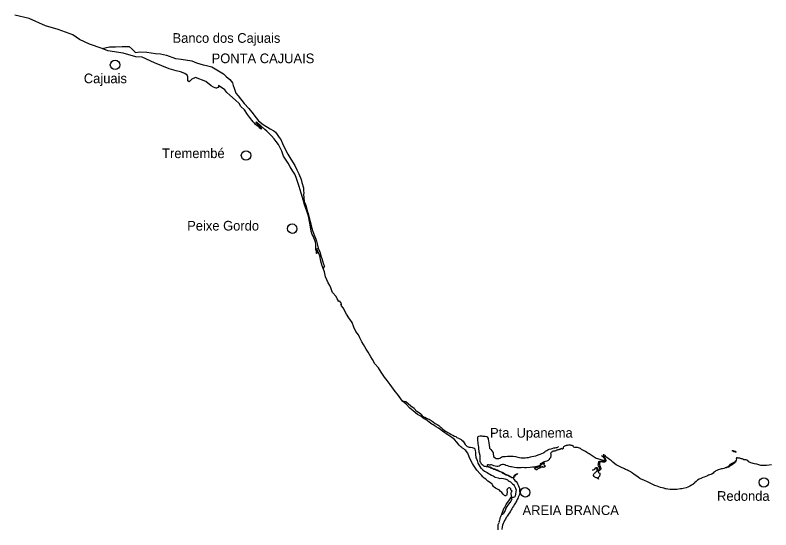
# Model space of a CAD drawing. Extents: x 662444 to 1640468, y 7452018 to 9606170.
# Drawn here: x 1338677 to 1392360, y 9444693 to 9481286 of the extents above; entities that cross this region are included whole.
import ezdxf

# ---------------------------------------------------------------- set-up
doc = ezdxf.new("R2010")
doc.units = 0
for name, color, linetype in [('Level 1', 7, 'Continuous'), ('Level 2', 7, 'Continuous'), ('Level 3', 7, 'Continuous')]:
    doc.layers.add(name, color=color, linetype=linetype)

msp = doc.modelspace()

# ---------------------------------------------------------------- linework, layer by layer
at = {"layer": 'Level 1'}
for points in [[(1343968, 9479211), (1343241, 9479552), (1342767, 9479891), (1341741, 9480268), (1340827, 9480522), (1339680, 9481054), (1338660, 9481286)], [(1352611, 9476253), (1352225, 9476558), (1351497, 9476851), (1351236, 9476724), (1351040, 9476548), (1350934, 9476622), (1350938, 9476906), (1350907, 9477028), (1350731, 9477144), (1350431, 9477244), (1350124, 9477321), (1349614, 9477465), (1348571, 9477892), (1347708, 9478299), (1347253, 9478321), (1346355, 9478583), (1345253, 9478742), (1344858, 9478909), (1343968, 9479211)], [(1344858, 9478909), (1345388, 9479041), (1345817, 9479027), (1346273, 9479062), (1346491, 9479060), (1346784, 9479064), (1347001, 9478865), (1347226, 9478636)], [(1347226, 9478636), (1347534, 9478676), (1348038, 9478644), (1348649, 9478563), (1349003, 9478532), (1349430, 9478431), (1350066, 9478211), (1350472, 9478156), (1351235, 9478026), (1351561, 9477900), (1352041, 9477758), (1352262, 9477695), (1352639, 9477607), (1353478, 9477121), (1353677, 9476922), (1353939, 9476701), (1354129, 9476469), (1354158, 9476279), (1354232, 9476086), (1354360, 9475729), (1354514, 9475552), (1354945, 9475012), (1355286, 9474637), (1355581, 9474263), (1355627, 9474189), (1355971, 9473777), (1356300, 9473517), (1356798, 9473190), (1357063, 9473051), (1357163, 9472966), (1357281, 9472791), (1357434, 9472595), (1357555, 9472448), (1357665, 9472148), (1357866, 9471762), (1358055, 9471397), (1358256, 9471035), (1358538, 9470606), (1358688, 9470297), (1358828, 9470009), (1358989, 9469602), (1359047, 9469392), (1359152, 9469017), (1359169, 9468847), (1359190, 9468596), (1359162, 9468567), (1359185, 9468300), (1359217, 9468047), (1359278, 9467886), (1359351, 9467686), (1359397, 9467466), (1359451, 9467299), (1359493, 9467178), (1359615, 9466674), (1359659, 9466543), (1359706, 9466316), (1359745, 9466150), (1359805, 9465967), (1359948, 9465597), (1360024, 9465420), (1360096, 9465212), (1360158, 9464923), (1360210, 9464711), (1360298, 9464516), (1360355, 9464389), (1360397, 9464171), (1360469, 9463981), (1360514, 9463808), (1360577, 9463586), (1360664, 9463436), (1360564, 9463269)], [(1361860, 9460803), (1361803, 9460824), (1361821, 9460847), (1361760, 9460886), (1361775, 9460917), (1361719, 9460925), (1361719, 9460945), (1361688, 9460976), (1361667, 9460925), (1361631, 9460958), (1361616, 9461012), (1361547, 9461108), (1361478, 9461287), (1361225, 9461562), (1361169, 9461689), (1361108, 9461889), (1361024, 9462077), (1360909, 9462249), (1360822, 9462463), (1360723, 9462686), (1360647, 9463030), (1360564, 9463269), (1360464, 9463539), (1360385, 9463806), (1360315, 9464163), (1360160, 9464544), (1360134, 9464647), (1360103, 9464699), (1360109, 9464601), (1360119, 9464488), (1360118, 9464338), (1360092, 9464344), (1360093, 9464457), (1360074, 9464524), (1360047, 9464572), (1360032, 9464724), (1360033, 9464888), (1360027, 9465012), (1360003, 9465153), (1359949, 9465335), (1359850, 9465580), (1359783, 9465698), (1359698, 9465937), (1359647, 9466235), (1359610, 9466489), (1359516, 9467002), (1359407, 9467357), (1359295, 9467614), (1359240, 9467794), (1359155, 9468072), (1358996, 9468617), (1358856, 9469111), (1358737, 9469457), (1358640, 9469740), (1358553, 9469976), (1358408, 9470204), (1358204, 9470511), (1358081, 9470760), (1357751, 9471267), (1357632, 9471619), (1357390, 9472092), (1357217, 9472298), (1357087, 9472490), (1356881, 9472712), (1356555, 9473031), (1356414, 9473147), (1355850, 9473664), (1355786, 9473654), (1355776, 9473636), (1355822, 9473598), (1355860, 9473552), (1355942, 9473481), (1356042, 9473389), (1356153, 9473274), (1356173, 9473209), (1356155, 9473189), (1356132, 9473199), (1356067, 9473258), (1356019, 9473310), (1355872, 9473425), (1355750, 9473513), (1355673, 9473595), (1355576, 9473706), (1355317, 9474035), (1355174, 9474225), (1354965, 9474558), (1354716, 9474789), (1354596, 9475010), (1354327, 9475236), (1353930, 9475589), (1353715, 9475789), (1353574, 9475981), (1353133, 9476271), (1353112, 9476253), (1353120, 9476149), (1353079, 9476140), (1352989, 9476104), (1352951, 9476089), (1352884, 9476108), (1352770, 9476172), (1352611, 9476253)], [(1367500, 9452769), (1367270, 9452889), (1366949, 9453167), (1366717, 9453348), (1366458, 9453634), (1366198, 9453853), (1365849, 9454332), (1365681, 9454538), (1365308, 9455022), (1365101, 9455314), (1364911, 9455552), (1364685, 9455896), (1364496, 9456211), (1364234, 9456501), (1364053, 9456817), (1363941, 9456985), (1363760, 9457329), (1363617, 9457545), (1363415, 9457874), (1363297, 9458050), (1363158, 9458353), (1363078, 9458569), (1362887, 9458801), (1362747, 9459106), (1362615, 9459441), (1362389, 9459762), (1362213, 9460029), (1361989, 9460482), (1361853, 9460611), (1361803, 9460717), (1361854, 9460675), (1361859, 9460722), (1361810, 9460754), (1361860, 9460803)], [(1367482, 9452935), (1367204, 9453111), (1367013, 9453316), (1366786, 9453492), (1366607, 9453654), (1366428, 9453794), (1366198, 9453853)], [(1367482, 9452935), (1367500, 9452916), (1367597, 9452812), (1367676, 9452740), (1367777, 9452695), (1367889, 9452628), (1367983, 9452577), (1368085, 9452553), (1368293, 9452423), (1368393, 9452360), (1368523, 9452268), (1368654, 9452177), (1368777, 9452108), (1368866, 9452027), (1368933, 9451970), (1369045, 9451873), (1369164, 9451782), (1369256, 9451722), (1369339, 9451659), (1369417, 9451609), (1369545, 9451534), (1369655, 9451485), (1369758, 9451437), (1369891, 9451362), (1369980, 9451323), (1370064, 9451264), (1370168, 9451223), (1370273, 9451169), (1370351, 9451117), (1370408, 9451067), (1370491, 9450992), (1370564, 9450888), (1370651, 9450763), (1370718, 9450693), (1370782, 9450631), (1370848, 9450603), (1370918, 9450577), (1371012, 9450565), (1371130, 9450548), (1371274, 9450514), (1371312, 9450488), (1371335, 9450447), (1371351, 9450315), (1371370, 9450227), (1371380, 9450099), (1371386, 9450000), (1371392, 9449888), (1371405, 9449825), (1371438, 9449733), (1371486, 9449624), (1371554, 9449440), (1371619, 9449320), (1371683, 9449198), (1371766, 9449079), (1371802, 9449047), (1371888, 9448969), (1372014, 9448879), (1372108, 9448824), (1372199, 9448777), (1372305, 9448707), (1372406, 9448655), (1372521, 9448588), (1372627, 9448534), (1372693, 9448483), (1372779, 9448453), (1372989, 9448386), (1373108, 9448357), (1373258, 9448367), (1373362, 9448356), (1373460, 9448332), (1373531, 9448300), (1373598, 9448267), (1373647, 9448241), (1373697, 9448198), (1373767, 9448168), (1373858, 9448098), (1373936, 9448028), (1374012, 9447967), (1374088, 9447909), (1374127, 9447851), (1374175, 9447762), (1374219, 9447671), (1374246, 9447591), (1374259, 9447513), (1374252, 9447432), (1374239, 9447367), (1374225, 9447275), (1374212, 9447174), (1374206, 9447130), (1374171, 9447042), (1374128, 9447015), (1374053, 9447000), (1373985, 9446995), (1373942, 9446986), (1373940, 9446932), (1373958, 9446889), (1373888, 9446745), (1373814, 9446647), (1373734, 9446524), (1373671, 9446452), (1373603, 9446354)], [(1373207, 9445722), (1373246, 9445819), (1373271, 9445876), (1373304, 9445960), (1373377, 9446146), (1373418, 9446253), (1373451, 9446308), (1373513, 9446400), (1373563, 9446489), (1373657, 9446634), (1373744, 9446748), (1373836, 9446894), (1373886, 9446966), (1373933, 9447077), (1373928, 9447151), (1373918, 9447207), (1373910, 9447275), (1373916, 9447324), (1373938, 9447372), (1373978, 9447438), (1373970, 9447473), (1373941, 9447494), (1373917, 9447509), (1373894, 9447546), (1373886, 9447572), (1373877, 9447608), (1373840, 9447656), (1373805, 9447679), (1373770, 9447694), (1373744, 9447693), (1373699, 9447666), (1373676, 9447646), (1373637, 9447577), (1373609, 9447509), (1373620, 9447433), (1373630, 9447399), (1373638, 9447373), (1373634, 9447356), (1373619, 9447337), (1373611, 9447283), (1373606, 9447239), (1373598, 9447178), (1373585, 9447145), (1373564, 9447132), (1373527, 9447120), (1373484, 9447125), (1373438, 9447141), (1373387, 9447186), (1373333, 9447241), (1373238, 9447349), (1373132, 9447447), (1373049, 9447537), (1373000, 9447567), (1372809, 9447662), (1372695, 9447733), (1372658, 9447789), (1372593, 9447903), (1372554, 9447947), (1372435, 9448044), (1372265, 9448168), (1372105, 9448291), (1372002, 9448368), (1371902, 9448470), (1371803, 9448580), (1371712, 9448684), (1371463, 9448944), (1371322, 9449152), (1371237, 9449297), (1371173, 9449412), (1371004, 9449716), (1370939, 9449879), (1370830, 9450136), (1370742, 9450267), (1370689, 9450334), (1370622, 9450388), (1370550, 9450446), (1370458, 9450511), (1370404, 9450544), (1370333, 9450607), (1370274, 9450668), (1370220, 9450724), (1370046, 9450924), (1369883, 9451109), (1369787, 9451198), (1369695, 9451258), (1369481, 9451397), (1369404, 9451450), (1369299, 9451524), (1369175, 9451611), (1369067, 9451684), (1368917, 9451796), (1368744, 9451933), (1368578, 9452027), (1368367, 9452162), (1368286, 9452215), (1368092, 9452359), (1367850, 9452535), (1367783, 9452561), (1367666, 9452636), (1367500, 9452769)], [(1374048, 9448399), (1374017, 9448385), (1373934, 9448425), (1373803, 9448488), (1373671, 9448554), (1373568, 9448588), (1373448, 9448646), (1373385, 9448677), (1373307, 9448727), (1373217, 9448788), (1373130, 9448830), (1373082, 9448844), (1373010, 9448879), (1372858, 9448937), (1372795, 9448960), (1372684, 9448998), (1372621, 9449030), (1372547, 9449059), (1372462, 9449085), (1372388, 9449119), (1372303, 9449153), (1372245, 9449168), (1372165, 9449178), (1372087, 9449188), (1372026, 9449199), (1371961, 9449224), (1371916, 9449266), (1371849, 9449322), (1371803, 9449373), (1371777, 9449427), (1371744, 9449488), (1371707, 9449564), (1371703, 9449648), (1371712, 9449788), (1371711, 9449854), (1371702, 9449956), (1371685, 9450071), (1371670, 9450139), (1371648, 9450230), (1371640, 9450306), (1371627, 9450442), (1371611, 9450566), (1371586, 9450690), (1371569, 9450834), (1371561, 9450930), (1371554, 9451018), (1371551, 9451112), (1371549, 9451208), (1371552, 9451273), (1371579, 9451332), (1371613, 9451352), (1371701, 9451373), (1371818, 9451379), (1371896, 9451356), (1371970, 9451345), (1372072, 9451344), (1372160, 9451330), (1372209, 9451307), (1372273, 9451200), (1372281, 9451140), (1372313, 9450997), (1372316, 9450897), (1372332, 9450827), (1372344, 9450749), (1372351, 9450688), (1372371, 9450578), (1372382, 9450513), (1372404, 9450470), (1372463, 9450408), (1372549, 9450323), (1372603, 9450230), (1372633, 9450185), (1372644, 9450131), (1372642, 9450070), (1372652, 9449957), (1372689, 9449879), (1372766, 9449822), (1372850, 9449778), (1372940, 9449769), (1373045, 9449777), (1373109, 9449798), (1373181, 9449847), (1373239, 9449885), (1373327, 9449905), (1373485, 9449910), (1373648, 9449928), (1373750, 9449938), (1373837, 9449944), (1373916, 9449944), (1374050, 9449928), (1374208, 9449899), (1374386, 9449861), (1374513, 9449839), (1374622, 9449823), (1374714, 9449814), (1374813, 9449812), (1374911, 9449824), (1375017, 9449837), (1375146, 9449848), (1375274, 9449875), (1375384, 9449905)], [(1375384, 9449905), (1375518, 9449927), (1375674, 9449969), (1375819, 9450025), (1375966, 9450079), (1376086, 9450129), (1376198, 9450167), (1376233, 9450192), (1376309, 9450247), (1376349, 9450289), (1376442, 9450345), (1376508, 9450390), (1376604, 9450424), (1376752, 9450462), (1376835, 9450490), (1376951, 9450523), (1377048, 9450537), (1377120, 9450550), (1377185, 9450560), (1377233, 9450582), (1377275, 9450614)], [(1378180, 9450700), (1378145, 9450716), (1378123, 9450712), (1378107, 9450729), (1378081, 9450715), (1378044, 9450740), (1378000, 9450714), (1377979, 9450733), (1377928, 9450703), (1377913, 9450709), (1377869, 9450695), (1377826, 9450694), (1377805, 9450680), (1377768, 9450685), (1377749, 9450670), (1377716, 9450645), (1377700, 9450636), (1377677, 9450631), (1377621, 9450602), (1377609, 9450557), (1377595, 9450557), (1377603, 9450520), (1377615, 9450497), (1377594, 9450475), (1377551, 9450442), (1377524, 9450460), (1377496, 9450471), (1377468, 9450446), (1377438, 9450447), (1377425, 9450432), (1377388, 9450428), (1377370, 9450412), (1377332, 9450412), (1377314, 9450396), (1377261, 9450395), (1377219, 9450376), (1377181, 9450361), (1377159, 9450360), (1377103, 9450340), (1377087, 9450323), (1377051, 9450321), (1377015, 9450299), (1376984, 9450299), (1376964, 9450281), (1376926, 9450287), (1376872, 9450278), (1376847, 9450248), (1376824, 9450247), (1376812, 9450221), (1376788, 9450221), (1376781, 9450201), (1376758, 9450196), (1376741, 9450179), (1376723, 9450150), (1376723, 9450136), (1376715, 9450116), (1376732, 9450084), (1376741, 9450069), (1376726, 9450038), (1376725, 9449979), (1376722, 9449904), (1376706, 9449864), (1376710, 9449837), (1376706, 9449814), (1376677, 9449794), (1376641, 9449768), (1376602, 9449728), (1376605, 9449702), (1376603, 9449681), (1376578, 9449664), (1376537, 9449633), (1376444, 9449580), (1376355, 9449551), (1376267, 9449522), (1376198, 9449503), (1376131, 9449470), (1376046, 9449423), (1375981, 9449378), (1375969, 9449316), (1375993, 9449303), (1376037, 9449320), (1376085, 9449360), (1376132, 9449388), (1376165, 9449410), (1376226, 9449451), (1376270, 9449448), (1376259, 9449420), (1376237, 9449391), (1376229, 9449349), (1376252, 9449289), (1376296, 9449244), (1376321, 9449236), (1376352, 9449222), (1376335, 9449201), (1376302, 9449176), (1376251, 9449162), (1376220, 9449142), (1376186, 9449131), (1376176, 9449137), (1376166, 9449156), (1376157, 9449182)], [(1379699, 9448941), (1379751, 9448958), (1379799, 9448979), (1379831, 9449010), (1379860, 9449057), (1379902, 9449107), (1379957, 9449118), (1379996, 9449126), (1380017, 9449117), (1380049, 9449063), (1380061, 9449017), (1380070, 9448981), (1380077, 9448931), (1380090, 9448896), (1380112, 9448900), (1380151, 9448923), (1380194, 9448963), (1380210, 9448997), (1380210, 9449031), (1380196, 9449082), (1380179, 9449141), (1380154, 9449182), (1380119, 9449244), (1380099, 9449291), (1380094, 9449312), (1380112, 9449329), (1380114, 9449339), (1380108, 9449379), (1380112, 9449442), (1380130, 9449511), (1380148, 9449547), (1380204, 9449589), (1380297, 9449585), (1380371, 9449578), (1380415, 9449572), (1380505, 9449571), (1380564, 9449581), (1380567, 9449607), (1380551, 9449626), (1380504, 9449636), (1380455, 9449636), (1380381, 9449647), (1380308, 9449677), (1380229, 9449701), (1380144, 9449716), (1380065, 9449741), (1379957, 9449778), (1379876, 9449817), (1379808, 9449872), (1379664, 9449959), (1379592, 9449998), (1379529, 9450042), (1379452, 9450101), (1379369, 9450145), (1379285, 9450195), (1379184, 9450263), (1379097, 9450308), (1379009, 9450361), (1378908, 9450417), (1378827, 9450472), (1378684, 9450531), (1378625, 9450543), (1378568, 9450545), (1378427, 9450548), (1378358, 9450572), (1378344, 9450593), (1378357, 9450619), (1378348, 9450629), (1378334, 9450654), (1378315, 9450654), (1378291, 9450670), (1378252, 9450677), (1378244, 9450691), (1378180, 9450700)], [(1381558, 9449221), (1381462, 9449267), (1381374, 9449324), (1381276, 9449390), (1381141, 9449503), (1381045, 9449598), (1380904, 9449695), (1380810, 9449769), (1380704, 9449840), (1380638, 9449896), (1380621, 9449914), (1380617, 9449949), (1380606, 9449966), (1380579, 9449989), (1380531, 9450004), (1380491, 9450022), (1380452, 9450038), (1380435, 9450029), (1380439, 9450016), (1380466, 9449998), (1380465, 9449978), (1380471, 9449949), (1380496, 9449917), (1380565, 9449822), (1380588, 9449769), (1380604, 9449722), (1380614, 9449679), (1380637, 9449637), (1380641, 9449589), (1380620, 9449554), (1380584, 9449525), (1380547, 9449516), (1380489, 9449515), (1380417, 9449517), (1380346, 9449534), (1380315, 9449540), (1380233, 9449515), (1380210, 9449493), (1380193, 9449460), (1380181, 9449414), (1380176, 9449385), (1380193, 9449324), (1380208, 9449262), (1380223, 9449199), (1380255, 9449125), (1380273, 9449075), (1380273, 9449013), (1380254, 9448977), (1380218, 9448934), (1380163, 9448898), (1380122, 9448878), (1380093, 9448852), (1380097, 9448824), (1380120, 9448769), (1380144, 9448749), (1380200, 9448719), (1380208, 9448695), (1380216, 9448636), (1380206, 9448586), (1380193, 9448542), (1380178, 9448507), (1380128, 9448455), (1380080, 9448380), (1380096, 9448355), (1380116, 9448300), (1380105, 9448310), (1380080, 9448332), (1380072, 9448337), (1380060, 9448364), (1380051, 9448378), (1380051, 9448380), (1380023, 9448386), (1379999, 9448386), (1379953, 9448398), (1379908, 9448412), (1379865, 9448433), (1379836, 9448456), (1379818, 9448480), (1379770, 9448563), (1379771, 9448598), (1379778, 9448653), (1379806, 9448695), (1379826, 9448725), (1379870, 9448760), (1379909, 9448790), (1379942, 9448824), (1379981, 9448852), (1380004, 9448874), (1380017, 9448902), (1380022, 9448937), (1380016, 9449016), (1380009, 9449047), (1379975, 9449096), (1379954, 9449099), (1379929, 9449095), (1379895, 9449069), (1379867, 9449026), (1379828, 9448982), (1379774, 9448951), (1379721, 9448942), (1379699, 9448941)], [(1380339, 9449974), (1380398, 9449925), (1380477, 9449850), (1380515, 9449782), (1380552, 9449741), (1380591, 9449696), (1380626, 9449634), (1380628, 9449609), (1380607, 9449589), (1380564, 9449581)], [(1389817, 9450278), (1389839, 9450278), (1389851, 9450277), (1389854, 9450265), (1389870, 9450263), (1389883, 9450251), (1389885, 9450234), (1389859, 9450228), (1389834, 9450230), (1389812, 9450242), (1389775, 9450239), (1389758, 9450251), (1389726, 9450252), (1389715, 9450273), (1389683, 9450274), (1389671, 9450292), (1389635, 9450287), (1389625, 9450305), (1389598, 9450306), (1389598, 9450321), (1389613, 9450317), (1389639, 9450331), (1389662, 9450315), (1389690, 9450327), (1389711, 9450305), (1389728, 9450311), (1389764, 9450295), (1389769, 9450279), (1389795, 9450276), (1389817, 9450278)], [(1376157, 9449182), (1376113, 9449188), (1376070, 9449161), (1375989, 9449116), (1375930, 9449079), (1375868, 9449055), (1375802, 9449022), (1375733, 9448973), (1375677, 9448968), (1375597, 9449025), (1375596, 9449025), (1375594, 9449060), (1375618, 9449094), (1375665, 9449124), (1375721, 9449137), (1375791, 9449146), (1375862, 9449175), (1375921, 9449197), (1375963, 9449210), (1375991, 9449232), (1375978, 9449252), (1375938, 9449253), (1375902, 9449248), (1375820, 9449228), (1375732, 9449202), (1375647, 9449178), (1375561, 9449161), (1375432, 9449142), (1375262, 9449117), (1375010, 9449107), (1374864, 9449108), (1374714, 9449117), (1374623, 9449110), (1374504, 9449103), (1374406, 9449097), (1374295, 9449095), (1374154, 9449125), (1374040, 9449149), (1373945, 9449165), (1373865, 9449176), (1373769, 9449196), (1373686, 9449237), (1373541, 9449280), (1373452, 9449310), (1373371, 9449338), (1373285, 9449334), (1373194, 9449308), (1373122, 9449276), (1373060, 9449229), (1372962, 9449198), (1372885, 9449195), (1372774, 9449214), (1372685, 9449244), (1372636, 9449264), (1372515, 9449326), (1372470, 9449318), (1372446, 9449308), (1372404, 9449297), (1372360, 9449301), (1372304, 9449311), (1372271, 9449326), (1372230, 9449321), (1372204, 9449289), (1372212, 9449250), (1372236, 9449229), (1372276, 9449206), (1372334, 9449183), (1372404, 9449174), (1372478, 9449148), (1372546, 9449094), (1372620, 9449068), (1372685, 9449045), (1372751, 9449024), (1372812, 9448991), (1372917, 9448958), (1372972, 9448935), (1373042, 9448902), (1373138, 9448855), (1373198, 9448825), (1373280, 9448789), (1373367, 9448738), (1373442, 9448701), (1373521, 9448658), (1373625, 9448603), (1373693, 9448580), (1373756, 9448559), (1373814, 9448522), (1373865, 9448492), (1373970, 9448425), (1374048, 9448399), (1374070, 9448407), (1374101, 9448442), (1374108, 9448463), (1374120, 9448492), (1374134, 9448542), (1374159, 9448581), (1374191, 9448613), (1374211, 9448633), (1374266, 9448664), (1374309, 9448684), (1374365, 9448699)], [(1390443, 9449683), (1390399, 9449711), (1390373, 9449725), (1390327, 9449736), (1390258, 9449755), (1390203, 9449777), (1390158, 9449781), (1390097, 9449788), (1390034, 9449800), (1389984, 9449821), (1389948, 9449822), (1389911, 9449805), (1389887, 9449775), (1389917, 9449742), (1389902, 9449652), (1389876, 9449557), (1389840, 9449518), (1389817, 9449490), (1389766, 9449440), (1389666, 9449356), (1389612, 9449320), (1389516, 9449274), (1389453, 9449228), (1389390, 9449182), (1389348, 9449160), (1389245, 9449130), (1389179, 9449121), (1389117, 9449106), (1389079, 9449091), (1389012, 9449061), (1388932, 9449040), (1388852, 9449024), (1388779, 9449006), (1388617, 9448962), (1388513, 9448926), (1388446, 9448895), (1388391, 9448854), (1388311, 9448788), (1388256, 9448729), (1388154, 9448661), (1387938, 9448577), (1387859, 9448534), (1387739, 9448492), (1387616, 9448437), (1387530, 9448406), (1387429, 9448380), (1387378, 9448355), (1387271, 9448305), (1387140, 9448231), (1387042, 9448145), (1386956, 9448064), (1386925, 9448026), (1386845, 9447941), (1386812, 9447912), (1386710, 9447868), (1386593, 9447797), (1386450, 9447726), (1386341, 9447686), (1386134, 9447638), (1386024, 9447617), (1385928, 9447604), (1385675, 9447569), (1385546, 9447566), (1385416, 9447568), (1385199, 9447571), (1385048, 9447580), (1384917, 9447606), (1384858, 9447617), (1384828, 9447625), (1384752, 9447648), (1384645, 9447674), (1384514, 9447703), (1384410, 9447743), (1384278, 9447790), (1384114, 9447853), (1384031, 9447900), (1383920, 9447937), (1383822, 9447984), (1383730, 9448033), (1383647, 9448077), (1383551, 9448122), (1383434, 9448173), (1383343, 9448219), (1383150, 9448288), (1383042, 9448347), (1382923, 9448441), (1382828, 9448504), (1382658, 9448620), (1382530, 9448734), (1382466, 9448782), (1382412, 9448813), (1382329, 9448859), (1382249, 9448892), (1382181, 9448930), (1382111, 9448961), (1382034, 9448989), (1381961, 9449032), (1381866, 9449083), (1381791, 9449112), (1381694, 9449164), (1381558, 9449221)], [(1389179, 9449121), (1389205, 9449137), (1389286, 9449187), (1389348, 9449235), (1389434, 9449304), (1389489, 9449365), (1389568, 9449406), (1389699, 9449476), (1389741, 9449500), (1389789, 9449521), (1389820, 9449556), (1389847, 9449599), (1389860, 9449614), (1389902, 9449652)], [(1390714, 9449627), (1390643, 9449657), (1390604, 9449681), (1390544, 9449681), (1390492, 9449681), (1390443, 9449683)], [(1392406, 9449325), (1392048, 9449282), (1391845, 9449273), (1391657, 9449276), (1391353, 9449367), (1391187, 9449396), (1390936, 9449471), (1390785, 9449539), (1390714, 9449627)], [(1374365, 9448699), (1374337, 9448648), (1374307, 9448630), (1374270, 9448601), (1374227, 9448578), (1374183, 9448549), (1374162, 9448516), (1374142, 9448464), (1374125, 9448436), (1374093, 9448400), (1374070, 9448359), (1374076, 9448333), (1374095, 9448304), (1374100, 9448297), (1374129, 9448271), (1374177, 9448211), (1374262, 9448135), (1374328, 9448044), (1374371, 9447967), (1374438, 9447818), (1374460, 9447763), (1374498, 9447652), (1374501, 9447571), (1374495, 9447471), (1374504, 9447435), (1374521, 9447367), (1374548, 9447344), (1374541, 9447331), (1374522, 9447331), (1374518, 9447303), (1374525, 9447299), (1374507, 9447259), (1374499, 9447259), (1374494, 9447230), (1374506, 9447205), (1374458, 9447116), (1374436, 9447064), (1374413, 9447014), (1374375, 9446920), (1374334, 9446855), (1374307, 9446791), (1374246, 9446674), (1374215, 9446614), (1374172, 9446542), (1374135, 9446470), (1374073, 9446372), (1374012, 9446274), (1373968, 9446194), (1373922, 9446131), (1373896, 9446080), (1373869, 9446014), (1373802, 9445918), (1373770, 9445873), (1373722, 9445800), (1373679, 9445749), (1373632, 9445667), (1373603, 9445622), (1373568, 9445567), (1373502, 9445462), (1373435, 9445359), (1373387, 9445249), (1373345, 9445138), (1373304, 9445020), (1373275, 9444920), (1373264, 9444859), (1373260, 9444776), (1373257, 9444711)], [(1373603, 9446354), (1373529, 9446233), (1373477, 9446071), (1373446, 9446011), (1373374, 9445893), (1373341, 9445838), (1373291, 9445791), (1373265, 9445780), (1373246, 9445819)], [(1372991, 9444693), (1372980, 9444781), (1372980, 9444850), (1372977, 9444919), (1372978, 9445021), (1372980, 9445025), (1372987, 9445068), (1373011, 9445117), (1373028, 9445173), (1373062, 9445200), (1373072, 9445246), (1373068, 9445288), (1373064, 9445312), (1373070, 9445316), (1373086, 9445329), (1373101, 9445384), (1373121, 9445472), (1373138, 9445559), (1373174, 9445641), (1373207, 9445722)]]:
    msp.add_lwpolyline(points, dxfattribs=at)
at = {"layer": 'Level 2'}
for centre, major_axis in [((1345776, 9477746), (336, -3)), ((1355079, 9471311), (335, -3)), ((1358364, 9466107), (335, -3)), ((1391860, 9448068), (335, -3)), ((1374900, 9447364), (335, -3))]:
    msp.add_ellipse(centre, major_axis=major_axis, ratio=0.999998, dxfattribs=at)

# ---------------------------------------------------------------- texts
at = {"layer": 'Level 3'}
for s, height, p in [('Banco dos Cajuais', 686.94, (1349859, 9479316)), ('PONTA CAJUAIS', 686.94, (1352632, 9477869)), ('Cajuais', 686.8, (1343556, 9476444)), ('Tremembé', 686.8, (1349119, 9471121)), ('Peixe Gordo', 686.81, (1350898, 9465972)), ('Pta. Upanema', 686.99, (1372409, 9451252)), ('Redonda', 687.2, (1388538, 9446760)), ('AREIA BRANCA', 686.98, (1374720, 9445750))]:
    msp.add_text(s, height=height, dxfattribs=at).set_placement(p)

doc.saveas('drawing.dxf')
